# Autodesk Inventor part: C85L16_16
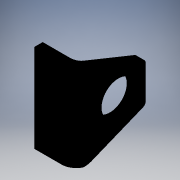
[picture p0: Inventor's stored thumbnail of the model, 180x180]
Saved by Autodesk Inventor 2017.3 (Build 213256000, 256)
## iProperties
Part Number: C85L16_16
Material: Generic
Catalog Web Link: www.cadenas.de
Description: C85 FOOT-Foot
Vendor: SMC
Document SubType Name: Modeling
Designer: partserver
Manufacturer: SMC
Mass: 5.51477 g
Surface Area: 37.2935 cm^2
Volume: 5.51477 cm^3
Density: 1 g/cm^3
Appearance: PSOLRGB-0-0-0
Category: PARTsolutions
Company: SMC
Title: C85L16
Author: Cadenas PARTsolutions
Comments: Foot
PSOL_IDENT_0: {$CADENAS_DATA\23d-libs\smc_jp\actuator\standard_air_cylinder\c85\accessories\c85_foot.prj},157 {VTY
PSOL_IDENT_1: P=3D},{NB=C85L16_16},{LINA=C85L16},{NN=C85 FOOT},{DATE=16.11.2020 04:36:14},{GEOMDATE=13.04.2020 02:
PSOL_IDENT_2: 43:45},{VERSION=},{LINEID=40},{WBVAR=},{WBNUMERIC=}  {NB=C85L16_16},{LINA=C85L16},{KT=DUMMY},{MODEL=
PSOL_IDENT_3: C85L16},{BORE=16},{AB=5.5},{AO=6},{AV=14},{BE=16},{LT=4.0},{NH=20},{TR=32},{UR=33},{US=42},{X1=22.00
PSOL_IDENT_4: 0},{X2=4.000},{X3=14.000},{ORDER=C85L16}
NB: C85L16_16
NN: C85 FOOT
NT: Foot
NBSYN: $MODEL._$BORE.
LINA: C85L16
CATALOG: SMC (JP
MODEL: C85L16
BORE: 16
AB: 5.5
AO: 6
AV: 14
BE: 16
LT: 4
NH: 20
TR: 32
UR: 33
US: 42
SUPPLIER: SMC
ARTICLENO: C85L16_16
BOMINFO: C85L16
CREATOR: CADENAS GmbH
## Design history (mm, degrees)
sketch "Sketch_1"
  geometry: L1 (-2, 13)-(-2, -13); L2 (5, -20)-(18, -20); L3 (18, -20)-(18, -16); L4 (18, -16)-(5, -16); L5 (2, -13)-(2, 13); L6 (2, 13)-(-2, 13); A1 r 7 centre (5, -13) between (-2, -13) and (5, -20); A2 r 3 centre (5, -13) between (2, -13) and (5, -16)
  constraints: 12 end point, 4 point on circle, 2 centre point
extrude "Extrusion1" join sketch "Sketch_1" stored distance "d0" = 42; taper "d1" = 0 deg
sketch "Sketch_2"
  geometry: C1 r 2.75 at (-12, 16); 1 further point
  constraints: 1 centre point
extrude "Extrusion2" cut sketch "Sketch_2" stored distance "d2" = 42; taper "d3" = 0 deg
sketch "Sketch_3"
  geometry: C1 r 2.75 at (-12, -16); 1 further point
  constraints: 1 centre point
extrude "Extrusion3" cut sketch "Sketch_3" stored distance "d4" = 42; taper "d5" = 0 deg
sketch "Sketch_4"
  geometry: L1 (18, 21)-(-16, 21); L2 (-16, 21)-(11.749, 9.789); L3 (13, 7.934)-(13, -7.934); L4 (11.749, -9.789)-(-16, -21); L5 (-16, -21)-(18, -21); L6 (18, -21)-(18, 21); A1 r 2 centre (11, 7.934) between (13, 7.934) and (11.749, 9.789); A2 r 2 centre (11, -7.934) between (11.749, -9.789) and (13, -7.934)
  constraints: 12 end point, 4 point on circle, 2 centre point
extrude "Extrusion4" cut sketch "Sketch_4" stored distance "d6" = 18; taper "d7" = 0 deg
sketch "Sketch_5"
  geometry: C1 r 8 at (0, 0); 1 further point
  constraints: 1 centre point
extrude "Extrusion5" cut sketch "Sketch_5" stored distance "d8" = 8; taper "d9" = 0 deg
node "Foot_Body_XY"
node "Foot_Body_YZ"
node "Foot_Body_ZX"
node "Foot_Body_X"
node "Foot_Body_Y"
node "Foot_Body_Z"
node "Foot_Body_Center"
node "UR_1_XY"
node "UR_1_YZ"
node "UR_1_ZX"
node "UR_1_X"
node "UR_1_Y"
node "UR_1_Z"
node "UR_1_Center"
node "UR_2_XY"
node "UR_2_YZ"
node "UR_2_ZX"
node "UR_2_X"
node "UR_2_Y"
node "UR_2_Z"
node "UR_2_Center"
body "Solid1"
other parameters: "d10" = 0
